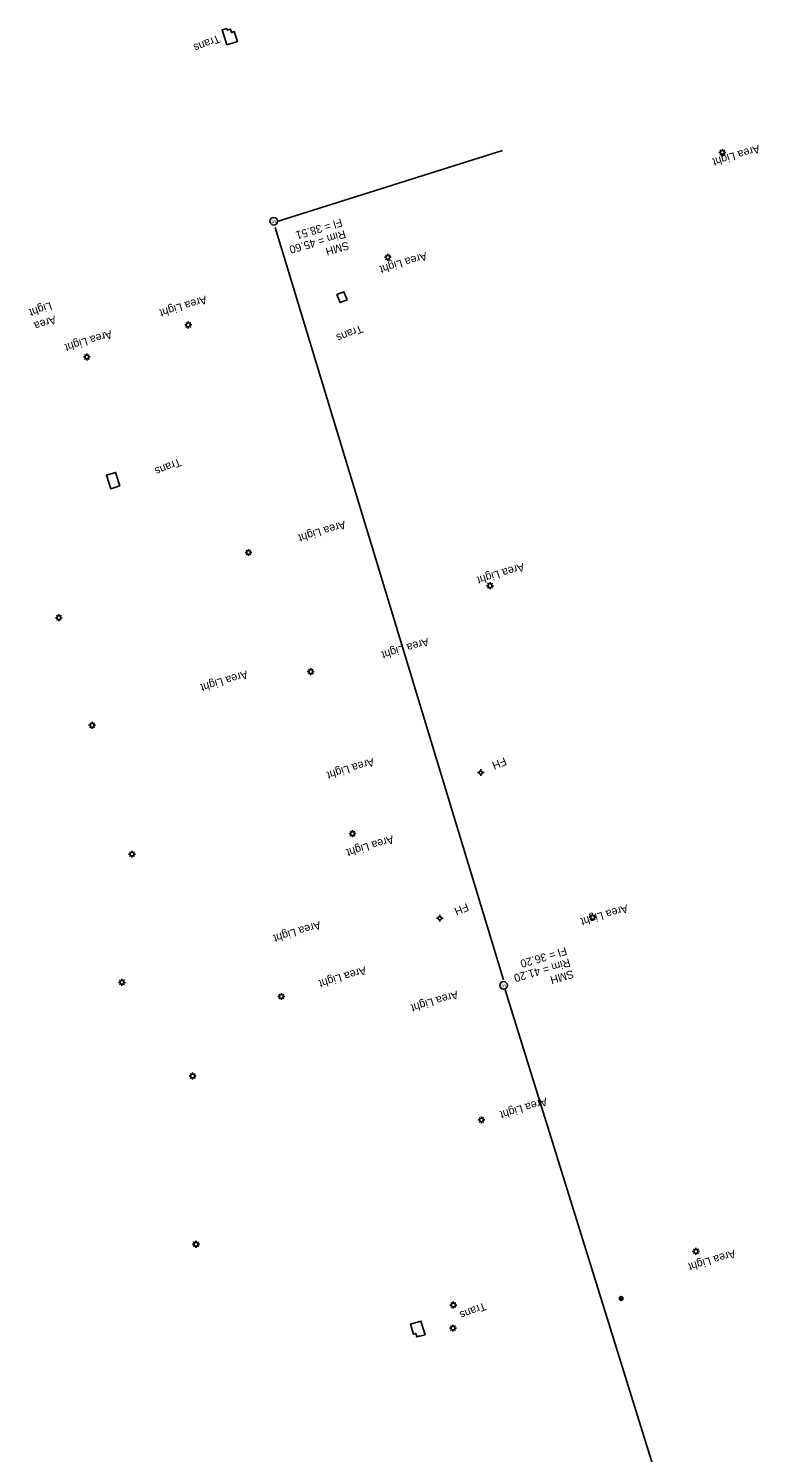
# Model space of a CAD drawing. Extents: x 3872070 to 3879223, y 293944 to 310567.
# Drawn here: x 3876011 to 3876285, y 302295 to 302829 of the extents above; entities that cross this region are included whole.
import ezdxf

# ---------------------------------------------------------------- set-up
doc = ezdxf.new("R2010")
doc.units = 0
for name, color, linetype in [('Level 3', 7, 'Continuous'), ('Level 33', 7, 'Continuous'), ('Level 34', 7, 'Continuous'), ('Level 35', 7, 'Continuous'), ('Level 4', 7, 'Continuous'), ('Level 5', 7, 'Continuous')]:
    doc.layers.add(name, color=color, linetype=linetype)

msp = doc.modelspace()

# ---------------------------------------------------------------- linework, layer by layer
at = {"layer": 'Level 3'}
for p, q in [((3876104.24, 302756.62), (3876188.75, 302783.18)), ((3876189.12, 302472.29), (3876103.5, 302754.41)), ((3876277.89, 302185), (3876189.68, 302468.6))]:
    msp.add_line(p, q, dxfattribs=at)
for centre in [(3876102.95, 302756.7), (3876189.13, 302470.2)]:
    msp.add_circle(centre, 1.41, dxfattribs=at)
at = {"layer": 'Level 4'}
for p, q in [((3876270.42, 302782.46), (3876269.85, 302782.46)), ((3876270.63, 302782.97), (3876270.23, 302783.38)), ((3876270.23, 302781.54), (3876270.63, 302781.94)), ((3876271.15, 302783.18), (3876271.15, 302783.76)), ((3876271.15, 302781.73), (3876271.15, 302781.16)), ((3876271.66, 302782.97), (3876272.07, 302783.38)), ((3876272.07, 302781.54), (3876271.66, 302781.94)), ((3876271.87, 302782.46), (3876272.45, 302782.46)), ((3876145.22, 302743.71), (3876144.82, 302744.11)), ((3876145.74, 302743.92), (3876145.74, 302744.49)), ((3876146.25, 302743.71), (3876146.66, 302744.11)), ((3876145.01, 302743.19), (3876144.44, 302743.19)), ((3876144.82, 302742.27), (3876145.22, 302742.68)), ((3876145.74, 302742.47), (3876145.74, 302741.89)), ((3876146.66, 302742.27), (3876146.25, 302742.68)), ((3876146.46, 302743.19), (3876147.04, 302743.19)), ((3876070.21, 302717.85), (3876069.63, 302717.85)), ((3876070.42, 302718.37), (3876070.02, 302718.77)), ((3876070.02, 302716.93), (3876070.42, 302717.34)), ((3876070.93, 302718.58), (3876070.93, 302719.15)), ((3876071.45, 302718.37), (3876071.85, 302718.77)), ((3876071.85, 302716.93), (3876071.45, 302717.34)), ((3876071.66, 302717.85), (3876072.23, 302717.85)), ((3876070.93, 302717.13), (3876070.93, 302716.55)), ((3876032.41, 302706.36), (3876032, 302706.77)), ((3876032.92, 302706.58), (3876032.92, 302707.15)), ((3876033.43, 302706.36), (3876033.84, 302706.77)), ((3876032.19, 302705.85), (3876031.62, 302705.85)), ((3876032, 302704.93), (3876032.41, 302705.34)), ((3876032.92, 302705.13), (3876032.92, 302704.55)), ((3876033.84, 302704.93), (3876033.43, 302705.34)), ((3876033.64, 302705.85), (3876034.22, 302705.85)), ((3876092.8, 302632.51), (3876092.22, 302632.51)), ((3876093.01, 302633.02), (3876092.6, 302633.43)), ((3876092.6, 302631.59), (3876093.01, 302632)), ((3876093.52, 302633.23), (3876093.52, 302633.81)), ((3876094.03, 302633.02), (3876094.44, 302633.43)), ((3876094.44, 302631.59), (3876094.03, 302632)), ((3876094.25, 302632.51), (3876094.82, 302632.51)), ((3876093.52, 302631.78), (3876093.52, 302631.21)), ((3876184.05, 302620.81), (3876184.05, 302621.38)), ((3876183.32, 302620.08), (3876182.75, 302620.08)), ((3876183.54, 302620.6), (3876183.13, 302621)), ((3876183.13, 302619.16), (3876183.54, 302619.57)), ((3876184.05, 302619.36), (3876184.05, 302618.78)), ((3876184.56, 302620.6), (3876184.97, 302621)), ((3876184.97, 302619.16), (3876184.56, 302619.57)), ((3876184.77, 302620.08), (3876185.35, 302620.08)), ((3876021.7, 302608.05), (3876021.12, 302608.05)), ((3876021.91, 302608.56), (3876021.5, 302608.97)), ((3876021.5, 302607.13), (3876021.91, 302607.53)), ((3876022.42, 302608.77), (3876022.42, 302609.35)), ((3876022.42, 302607.32), (3876022.42, 302606.75)), ((3876022.93, 302608.56), (3876023.34, 302608.97)), ((3876023.34, 302607.13), (3876022.93, 302607.53)), ((3876023.15, 302608.05), (3876023.72, 302608.05)), ((3876116.86, 302588.58), (3876116.86, 302589.16)), ((3876116.13, 302587.86), (3876115.56, 302587.86)), ((3876116.35, 302588.37), (3876115.94, 302588.78)), ((3876115.94, 302586.94), (3876116.35, 302587.34)), ((3876116.86, 302587.13), (3876116.86, 302586.56)), ((3876117.37, 302588.37), (3876117.78, 302588.78)), ((3876117.78, 302586.94), (3876117.37, 302587.34)), ((3876117.58, 302587.86), (3876118.16, 302587.86)), ((3876034.39, 302568.24), (3876033.98, 302568.65)), ((3876034.9, 302568.45), (3876034.9, 302569.03)), ((3876035.41, 302568.24), (3876035.82, 302568.65)), ((3876034.18, 302567.73), (3876033.6, 302567.73)), ((3876033.98, 302566.81), (3876034.39, 302567.22)), ((3876034.9, 302567), (3876034.9, 302566.43)), ((3876035.82, 302566.81), (3876035.41, 302567.22)), ((3876035.62, 302567.73), (3876036.2, 302567.73)), ((3876131.77, 302527.11), (3876131.2, 302527.11)), ((3876131.98, 302527.62), (3876131.58, 302528.03)), ((3876131.58, 302526.19), (3876131.98, 302526.6)), ((3876132.5, 302527.84), (3876132.5, 302528.41)), ((3876132.5, 302526.39), (3876132.5, 302525.81)), ((3876133.01, 302527.62), (3876133.42, 302528.03)), ((3876133.42, 302526.19), (3876133.01, 302526.6)), ((3876133.22, 302527.11), (3876133.8, 302527.11)), ((3876049.29, 302519.92), (3876048.88, 302520.32)), ((3876049.8, 302520.13), (3876049.8, 302520.71)), ((3876050.31, 302519.92), (3876050.72, 302520.32)), ((3876049.08, 302519.41), (3876048.5, 302519.41)), ((3876048.88, 302518.49), (3876049.29, 302518.89)), ((3876049.8, 302518.68), (3876049.8, 302518.1)), ((3876050.72, 302518.49), (3876050.31, 302518.89)), ((3876050.53, 302519.41), (3876051.1, 302519.41)), ((3876221.78, 302495.73), (3876221.2, 302495.73)), ((3876221.99, 302496.24), (3876221.58, 302496.65)), ((3876221.58, 302494.81), (3876221.99, 302495.22)), ((3876222.5, 302496.45), (3876222.5, 302497.03)), ((3876222.5, 302495), (3876222.5, 302494.43)), ((3876223.02, 302496.24), (3876223.42, 302496.65)), ((3876223.42, 302494.81), (3876223.02, 302495.22)), ((3876223.23, 302495.73), (3876223.8, 302495.73)), ((3876045.55, 302471.86), (3876045.14, 302472.26)), ((3876046.06, 302472.07), (3876046.06, 302472.64)), ((3876046.57, 302471.86), (3876046.98, 302472.26)), ((3876045.33, 302471.34), (3876044.76, 302471.34)), ((3876045.14, 302470.42), (3876045.55, 302470.83)), ((3876046.06, 302470.62), (3876046.06, 302470.04)), ((3876046.98, 302470.42), (3876046.57, 302470.83)), ((3876046.78, 302471.34), (3876047.36, 302471.34)), ((3876105.32, 302466.54), (3876104.91, 302466.95)), ((3876105.83, 302466.76), (3876105.83, 302467.33)), ((3876106.35, 302466.54), (3876106.75, 302466.95)), ((3876105.11, 302466.03), (3876104.53, 302466.03)), ((3876104.91, 302465.11), (3876105.32, 302465.52)), ((3876105.83, 302465.31), (3876105.83, 302464.73)), ((3876106.75, 302465.11), (3876106.35, 302465.52)), ((3876106.56, 302466.03), (3876107.13, 302466.03)), ((3876071.85, 302436.25), (3876071.28, 302436.25)), ((3876072.06, 302436.76), (3876071.66, 302437.17)), ((3876071.66, 302435.33), (3876072.06, 302435.74)), ((3876072.58, 302436.98), (3876072.58, 302437.55)), ((3876072.58, 302435.53), (3876072.58, 302434.95)), ((3876073.09, 302436.76), (3876073.5, 302437.17)), ((3876073.5, 302435.33), (3876073.09, 302435.74)), ((3876073.3, 302436.25), (3876073.88, 302436.25)), ((3876180.12, 302419.74), (3876179.54, 302419.74)), ((3876180.33, 302420.25), (3876179.93, 302420.66)), ((3876179.93, 302418.82), (3876180.33, 302419.22)), ((3876180.85, 302420.46), (3876180.85, 302421.04)), ((3876180.85, 302419.01), (3876180.85, 302418.44)), ((3876181.36, 302420.25), (3876181.76, 302420.66)), ((3876181.76, 302418.82), (3876181.36, 302419.22)), ((3876181.57, 302419.74), (3876182.15, 302419.74)), ((3876073.1, 302373.11), (3876072.53, 302373.11)), ((3876073.14, 302373.18), (3876072.56, 302373.18)), ((3876073.32, 302373.63), (3876072.91, 302374.03)), ((3876072.91, 302372.19), (3876073.32, 302372.6)), ((3876073.35, 302373.69), (3876072.94, 302374.1)), ((3876072.94, 302372.26), (3876073.35, 302372.66)), ((3876073.83, 302373.84), (3876073.83, 302374.41)), ((3876073.83, 302372.39), (3876073.83, 302371.81)), ((3876073.86, 302373.9), (3876073.86, 302374.48)), ((3876073.86, 302372.45), (3876073.86, 302371.88)), ((3876074.34, 302373.63), (3876074.75, 302374.03)), ((3876074.75, 302372.19), (3876074.34, 302372.6)), ((3876074.38, 302373.69), (3876074.78, 302374.1)), ((3876074.78, 302372.26), (3876074.38, 302372.66)), ((3876074.55, 302373.11), (3876075.13, 302373.11)), ((3876074.59, 302373.18), (3876075.16, 302373.18)), ((3876260.53, 302370.48), (3876259.96, 302370.48)), ((3876260.74, 302370.99), (3876260.34, 302371.4)), ((3876261.25, 302371.2), (3876261.25, 302371.78)), ((3876261.77, 302370.99), (3876262.17, 302371.4)), ((3876261.98, 302370.48), (3876262.56, 302370.48)), ((3876260.34, 302369.56), (3876260.74, 302369.96)), ((3876261.25, 302369.75), (3876261.25, 302369.18)), ((3876262.17, 302369.56), (3876261.77, 302369.96)), ((3876169.57, 302350.37), (3876168.99, 302350.37)), ((3876169.78, 302350.89), (3876169.38, 302351.29)), ((3876169.38, 302349.46), (3876169.78, 302349.86)), ((3876170.29, 302351.1), (3876170.29, 302351.67)), ((3876170.29, 302349.65), (3876170.29, 302349.07)), ((3876170.81, 302350.89), (3876171.21, 302351.29)), ((3876171.21, 302349.46), (3876170.81, 302349.86)), ((3876171.02, 302350.37), (3876171.59, 302350.37)), ((3876169.42, 302341.69), (3876168.85, 302341.69)), ((3876169.63, 302342.2), (3876169.23, 302342.61)), ((3876169.23, 302340.77), (3876169.63, 302341.18)), ((3876170.15, 302342.41), (3876170.15, 302342.99)), ((3876170.15, 302340.96), (3876170.15, 302340.39)), ((3876170.66, 302342.2), (3876171.06, 302342.61)), ((3876171.06, 302340.77), (3876170.66, 302341.18)), ((3876170.87, 302341.69), (3876171.45, 302341.69))]:
    msp.add_line(p, q, dxfattribs=at)
for points in [[(3876085.33, 302822.85), (3876089.34, 302824.09), (3876088.19, 302827.81), (3876087.1, 302827.48), (3876086.71, 302828.76), (3876085.54, 302828.4), (3876085.36, 302828.99), (3876083.59, 302828.45), (3876085.33, 302822.85)], [(3876130.46, 302727.28), (3876127.85, 302726.24), (3876126.66, 302729.23), (3876129.27, 302730.27), (3876130.46, 302727.28)], [(3876045.28, 302657.45), (3876041.85, 302656.36), (3876040.24, 302661.47), (3876043.66, 302662.55), (3876045.28, 302657.45)], [(3876159.67, 302339.23), (3876158.11, 302344.34), (3876154.19, 302343.15), (3876155.33, 302339.41), (3876156.22, 302339.68), (3876156.61, 302338.4), (3876157.74, 302338.75), (3876157.77, 302338.65), (3876159.67, 302339.23)]]:
    msp.add_lwpolyline(points, dxfattribs=at)
for centre in [(3876271.15, 302782.46), (3876145.74, 302743.19), (3876070.93, 302717.85), (3876032.92, 302705.85), (3876093.52, 302632.51), (3876184.05, 302620.08), (3876022.42, 302608.05), (3876116.86, 302587.86), (3876034.9, 302567.73), (3876132.5, 302527.11), (3876049.8, 302519.41), (3876222.5, 302495.73), (3876046.06, 302471.34), (3876105.83, 302466.03), (3876072.58, 302436.25), (3876180.85, 302419.74), (3876073.83, 302373.11), (3876073.86, 302373.18), (3876261.25, 302370.48), (3876170.29, 302350.37), (3876170.15, 302341.69)]:
    msp.add_circle(centre, 0.725, dxfattribs=at)
at = {"layer": 'Level 5'}
for p, q in [((3876179.29, 302550.01), (3876179.91, 302550.01)), ((3876180.54, 302551.26), (3876180.54, 302550.62)), ((3876180.54, 302549.38), (3876180.54, 302548.76)), ((3876181.15, 302550.01), (3876181.79, 302550.01)), ((3876163.98, 302495.4), (3876164.6, 302495.4)), ((3876165.23, 302496.65), (3876165.23, 302496.02)), ((3876165.23, 302494.78), (3876165.23, 302494.15)), ((3876165.85, 302495.4), (3876166.48, 302495.4)), ((3876232.73, 302352.8), (3876232.37, 302352.8)), ((3876233.73, 302352.8), (3876232.73, 302352.8)), ((3876234.09, 302352.8), (3876233.73, 302352.8))]:
    msp.add_line(p, q, dxfattribs=at)
for centre, radius in [((3876180.54, 302550.01), 0.625), ((3876165.23, 302495.4), 0.625), ((3876233.23, 302352.8), 0.7)]:
    msp.add_circle(centre, radius, dxfattribs=at)
msp.add_arc((3876233.23, 302352.8), 0.5, 180, 0, dxfattribs=at)

# ---------------------------------------------------------------- texts
at = {"layer": 'Level 3'}
for p in [(3876102.24, 302757.18), (3876188.42, 302470.68)]:
    msp.add_text('S', height=1.41, rotation=270, dxfattribs=at).set_placement(p)
at = {"layer": 'Level 33'}
for s, p in [('Fl = 38.51', (3876128.16, 302757.78)), ('Rim = 45.60', (3876129.42, 302753.46)), ('SMH', (3876130.68, 302749.14)), ('Fl = 36.20', (3876212.35, 302484.65)), ('Rim = 41.20', (3876213.61, 302480.33)), ('SMH', (3876214.88, 302476.01))]:
    msp.add_text(s, height=3, rotation=196.312, dxfattribs=at).set_placement(p)
at = {"layer": 'Level 34'}
for s, rotation, p in [('Trans', 202.1252, (3876082.12, 302826.7)), ('Area Light', 196.7611, (3876284.69, 302785.42)), ('Area Light', 196.7611, (3876159.92, 302745.15)), ('Area Light', 196.7611, (3876077.39, 302728.84)), ('Light', 199.0085, (3876019.23, 302726.48)), ('Area', 199.0085, (3876020.82, 302721.41)), ('Trans', 202.1252, (3876135.6, 302717.95)), ('Area Light', 196.7611, (3876041.88, 302715.9)), ('Trans', 202.1252, (3876067.56, 302667.92)), ('Area Light', 196.7611, (3876129.45, 302644.45)), ('Area Light', 196.7611, (3876196.39, 302628.63)), ('Area Light', 196.7611, (3876160.64, 302600.58)), ('Area Light', 196.7611, (3876092.74, 302588.35)), ('Area Light', 196.7611, (3876140.12, 302555.53)), ('Area Light', 196.7611, (3876147.45, 302526.49)), ('Area Light', 196.7611, (3876235.26, 302500.6)), ('Area Light', 196.7611, (3876120.09, 302494.36)), ('Area Light', 196.7611, (3876137.13, 302477.34)), ('Area Light', 196.7611, (3876171.61, 302468.25)), ('Area Light', 196.7611, (3876205.03, 302428.19)), ('Area Light', 196.7611, (3876275.57, 302371.13)), ('Trans', 201.6464, (3876181.87, 302351.46))]:
    msp.add_text(s, height=3, rotation=rotation, dxfattribs=at).set_placement(p)
at = {"layer": 'Level 35'}
for p in [(3876189.45, 302555.8), (3876175.29, 302501.14)]:
    msp.add_text('FH', height=3, rotation=202.0632, dxfattribs=at).set_placement(p)

doc.saveas('drawing.dxf')
